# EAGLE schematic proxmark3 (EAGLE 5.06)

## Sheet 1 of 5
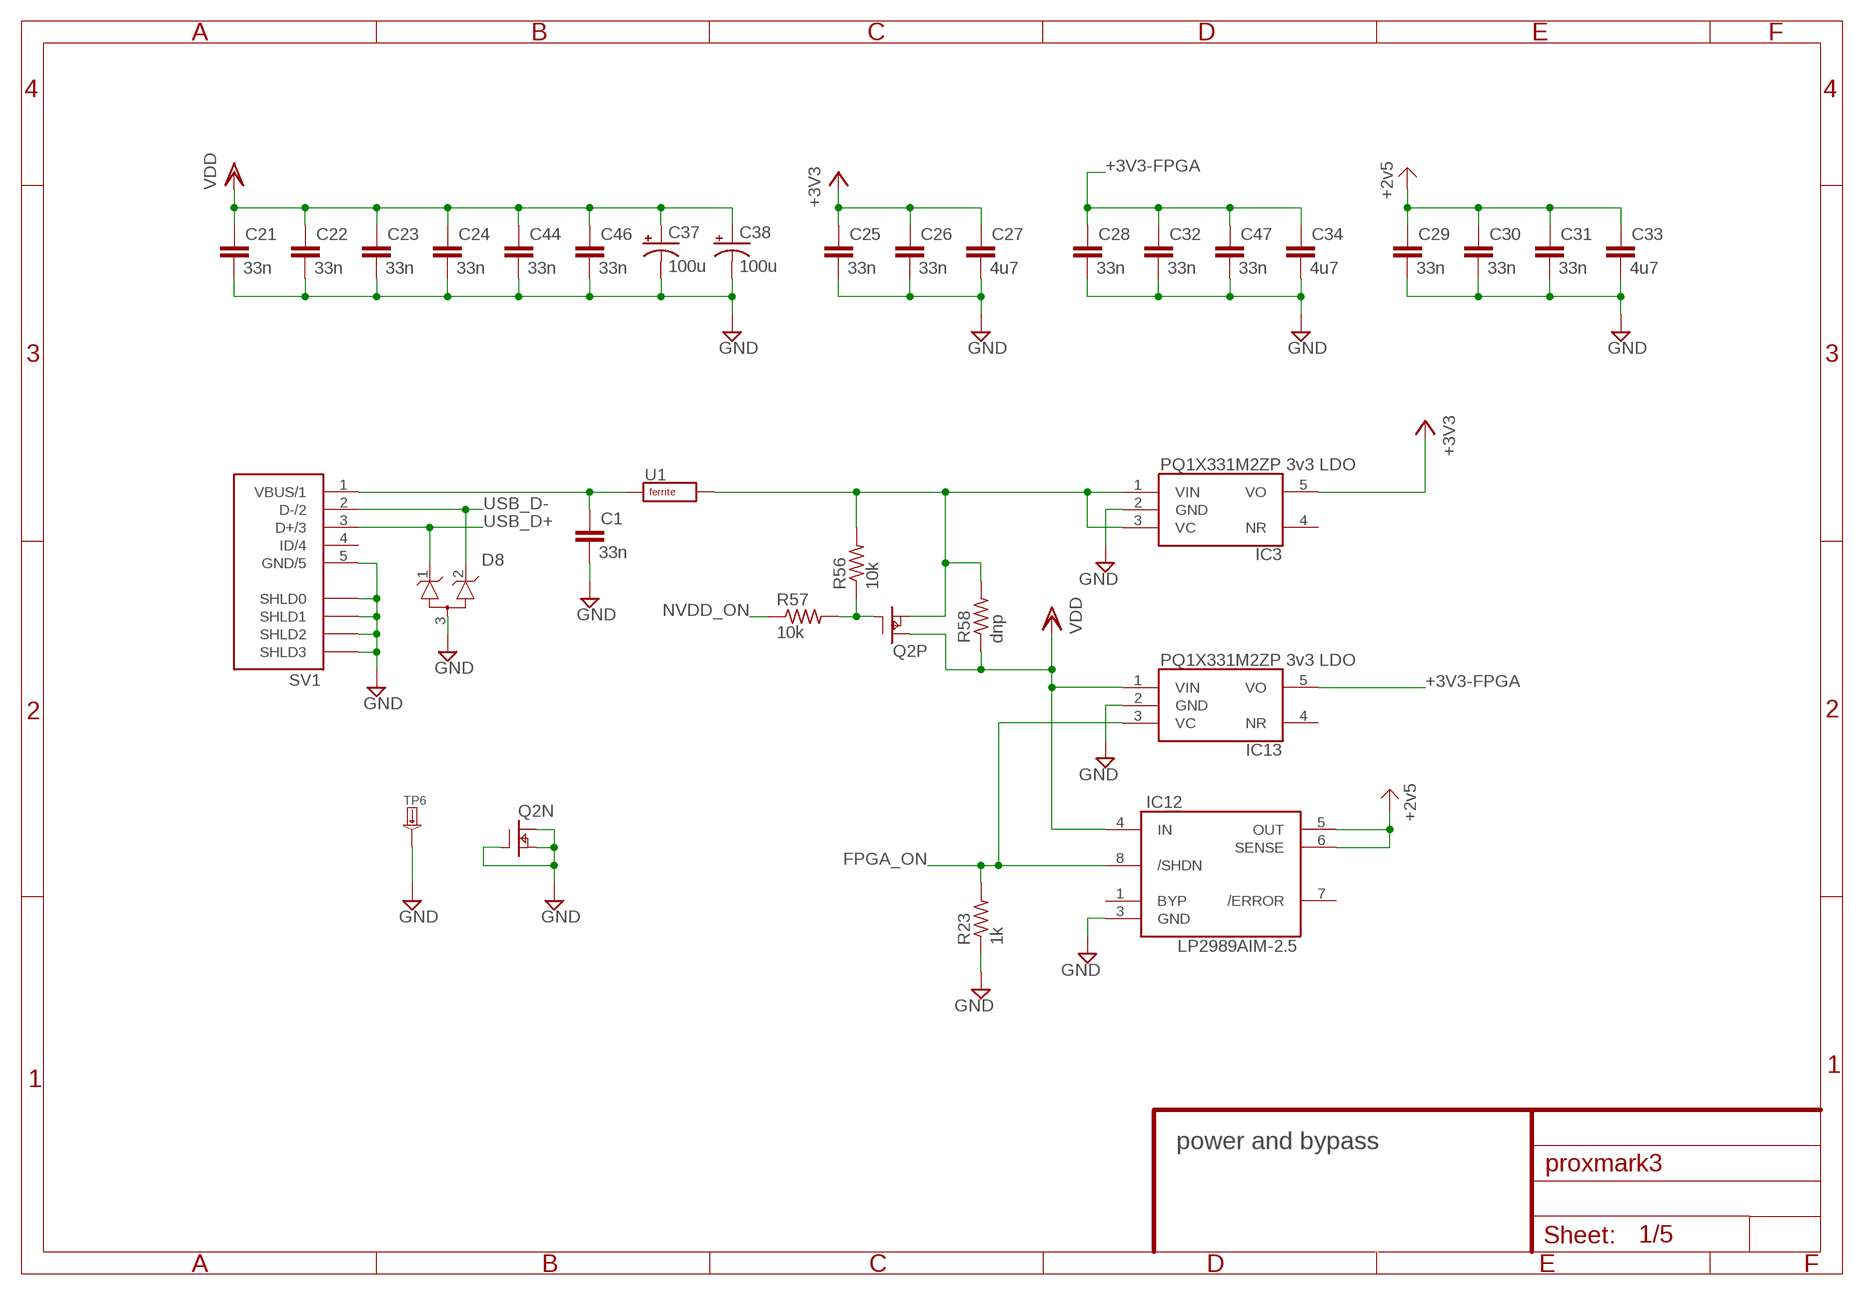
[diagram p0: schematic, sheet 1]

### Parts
C1  33n  CAPACITOR0603  [RLC_0603]
C21  33n  CAPACITOR0603  [RLC_0603]
C22  33n  CAPACITOR0603  [RLC_0603]
C23  33n  CAPACITOR0603  [RLC_0603]
C24  33n  CAPACITOR0603  [RLC_0603]
C25  33n  CAPACITOR0603  [RLC_0603]
C26  33n  CAPACITOR0603  [RLC_0603]
C27  4u7  CAPACITOR1210  [RLC_1210]
C28  33n  CAPACITOR0603  [RLC_0603]
C29  33n  CAPACITOR0603  [RLC_0603]
C30  33n  CAPACITOR0603  [RLC_0603]
C31  33n  CAPACITOR0603  [RLC_0603]
C32  33n  CAPACITOR0603  [RLC_0603]
C33  4u7  CAPACITOR1210  [RLC_1210]
C34  4u7  CAPACITOR1210  [RLC_1210]
C37  100u  CAPACITOR-POLARIZEDALCHIP-MZA-F80  [CAPCAITOR-ELECTROLYTIC-ALCHIP-MZA-F80]
C38  100u  CAPACITOR-POLARIZEDALCHIP-MZA-F80  [CAPCAITOR-ELECTROLYTIC-ALCHIP-MZA-F80]
C44  33n  CAPACITOR0603  [RLC_0603]
C46  33n  CAPACITOR0603  [RLC_0603]
C47  33n  CAPACITOR0603  [RLC_0603]
D8  DUAL-TVS-COMMON-ANODE  [SOT23-3LEAD]
IC3  PQ1X331M2ZP-3V3-LDO-SOT-23-5  [SOT-23-5]
IC12  LP2989AIM-2.5  LP2989-LDOSOIC  [SOIC-8]
IC13  PQ1X331M2ZP-3V3-LDO-SOT-23-5  [SOT-23-5]
Q2  IRF7307  [SOIC-8]
R23  1k  RESISTOR0603  [RLC_0603]
R56  10k  RESISTOR0603  [RLC_0603]
R57  10k  RESISTOR0603  [RLC_0603]
R58  dnp  RESISTOR0603  [RLC_0603]
SV1  USB-MINIB  [USB-MINIB-SMD]
TP6  TESTPADKEYSTONE-PTH  [KEYSTONE-PTH-TESTPOINT-5011]
U1  FERRITE0805  [RLC_0805]

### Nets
+2V5: C29.1 C30.1 C31.1 C33.1 IC12.5(OUT) IC12.6(SENSE) ; supply symbol labelled SUPPLY_2V5 ; also sheet 2
+3V3: C25.1 C26.1 C27.1 IC3.5(VO) ; also sheet 2,3
+3V3-FPGA: C28.1 C32.1 C34.1 C47.1 IC13.5(VO) ; also sheet 2
FPGA_ON: IC12.8(/SHDN) IC13.3(VC) R23.2 ; also sheet 3
GND: C1.2 C21.2 C22.2 C23.2 C24.2 C25.2 C26.2 C27.2 C28.2 C29.2 C30.2 C31.2 C32.2 C33.2 C34.2 C37.- C38.- C44.2 C46.2 C47.2 D8.3(A) IC3.2(GND) IC12.3(GND) IC13.2(GND) Q2.1(N:S) Q2.2(N:G) Q2.8(N:D) R23.1 SV1.5(GND/5) SV1.TAB0(SHLD0) SV1.TAB1(SHLD1) SV1.TAB2(SHLD2) SV1.TAB3(SHLD3) TP6.A ; also sheet 2,3,4,5
N$1: C1.1 SV1.1(VBUS/1) U1.1(A)
N$49: IC3.1(VIN) IC3.3(VC) Q2.3(P:S) R56.2 R58.2 U1.2(B)
NVDD_ON: R57.1 ; also sheet 3
PFETGATE: Q2.4(P:G) R56.1 R57.2
USB_D+: D8.1(K1) SV1.3(D+/3) ; also sheet 3
USB_D-: D8.2(K2) SV1.2(D-/2) ; also sheet 3
VDD: C21.1 C22.1 C23.1 C24.1 C37.+ C38.+ C44.1 C46.1 IC12.4(IN) IC13.1(VIN) Q2.6(P:D) R58.1 ; also sheet 2,4,5
Unconnected: IC3.4(NR) IC12.1(BYP) IC12.7(/ERROR) IC13.4(NR) SV1.4(ID/4)

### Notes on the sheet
- power and bypass

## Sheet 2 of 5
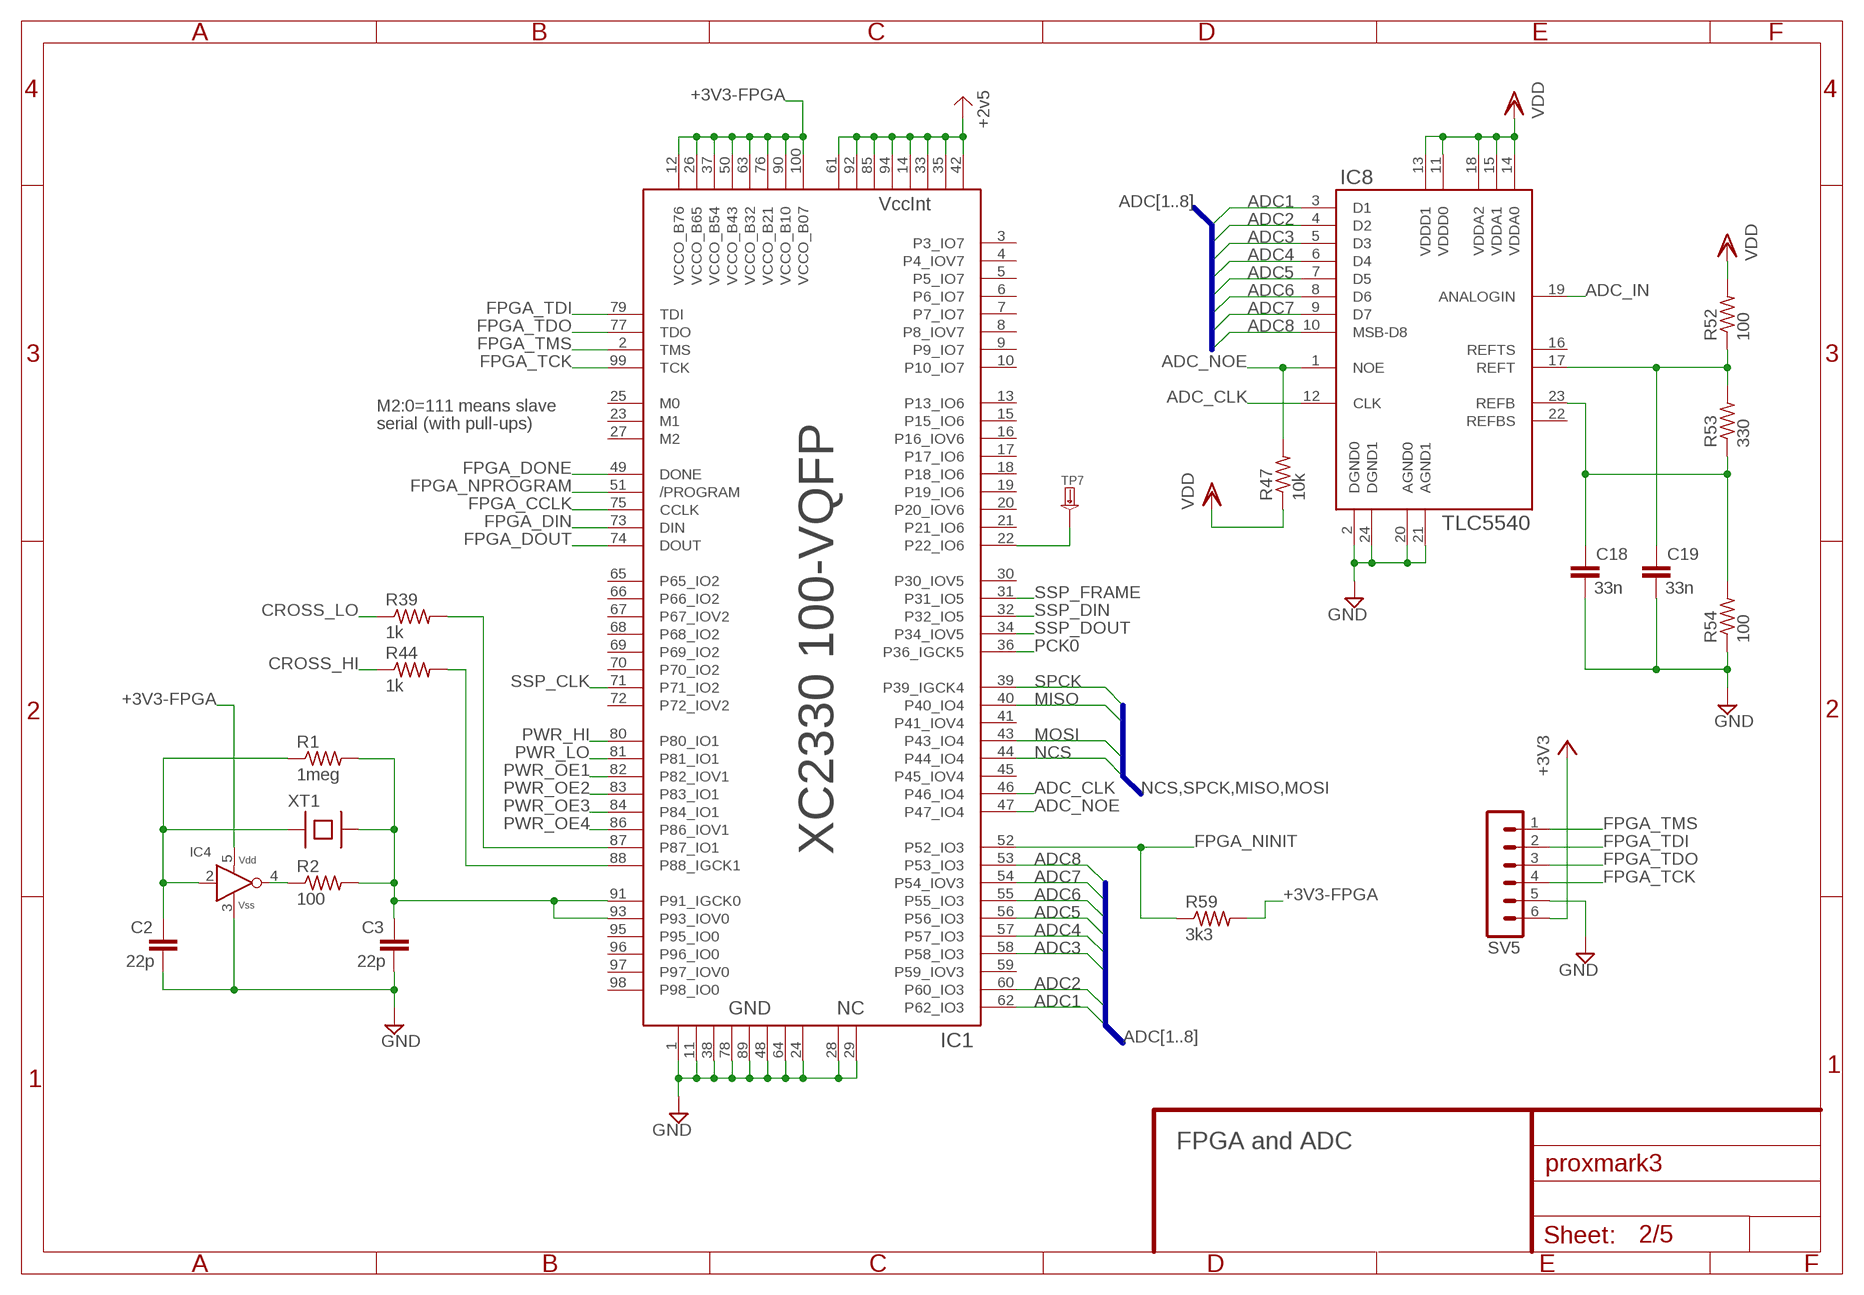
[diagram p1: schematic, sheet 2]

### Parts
C2  22p  CAPACITOR0603  [RLC_0603]
C3  22p  CAPACITOR0603  [RLC_0603]
C18  33n  CAPACITOR0603  [RLC_0603]
C19  33n  CAPACITOR0603  [RLC_0603]
IC1  SPARTAN-II-XC2S30-100-VQFP  [VQFP-100]
IC4  HCU-INVERTER  [SMV-5]
IC8  TLC5540  [TSSOP-24]
R1  1meg  RESISTOR0603  [RLC_0603]
R2  100  RESISTOR0603  [RLC_0603]
R39  1k  RESISTOR0603  [RLC_0603]
R44  1k  RESISTOR0603  [RLC_0603]
R47  10k  RESISTOR0603  [RLC_0603]
R52  100  RESISTOR0603  [RLC_0603]
R53  330  RESISTOR0603  [RLC_0603]
R54  100  RESISTOR0603  [RLC_0603]
R59  3k3  RESISTOR0603  [RLC_0603]
SV5  HEADER-MALE-6X1  [HEADER-MALE-6X1-0.100-UNKEYED]
TP7  TESTPADKEYSTONE-SMD  [KEYSTONE-SMD-TESTPOINT-5015]
XT1  XTAL-SMD-CITIZEN-CS10  [XTAL-SMD-CITIZEN-CS10]

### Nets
+2V5: IC1.14(VCCINT5) IC1.33(VCCINT6) IC1.35(VCCINT7) IC1.42(VCCINT8) IC1.61(VCCINT1) IC1.85(VCCINT3) IC1.92(VCCINT2) IC1.94(VCCINT4) ; supply symbol labelled SUPPLY_2V5 ; also sheet 1
+3V3: SV5.6 ; also sheet 1,3
+3V3-FPGA: IC1.12(VCCO_B76) IC1.26(VCCO_B65) IC1.37(VCCO_B54) IC1.50(VCCO_B43) IC1.63(VCCO_B32) IC1.76(VCCO_B21) IC1.90(VCCO_B10) IC1.100(VCCO_B07) IC4.5(VDD) R59.2 ; also sheet 1
ADC1: IC1.62(P62_IO3) IC8.3(D1)
ADC2: IC1.60(P60_IO3) IC8.4(D2)
ADC3: IC1.58(P58_IO3) IC8.5(D3)
ADC4: IC1.57(P57_IO3) IC8.6(D4)
ADC5: IC1.56(P56_IO3) IC8.7(D5)
ADC6: IC1.55(P55_IO3) IC8.8(D6)
ADC7: IC1.54(P54_IOV3) IC8.9(D7)
ADC8: IC1.53(P53_IO3) IC8.10(MSB-D8)
ADC_CLK: IC1.46(P46_IO4) IC8.12(CLK)
ADC_IN: IC8.19(ANALOGIN) ; also sheet 4
ADC_NOE: IC1.47(P47_IO4) IC8.1(NOE) R47.2
CROSS_HI: R44.1 ; also sheet 4
CROSS_LO: R39.1 ; also sheet 4
FPGA_CCLK: IC1.75(CCLK) ; also sheet 3
FPGA_DIN: IC1.73(DIN) ; also sheet 3
FPGA_DONE: IC1.49(DONE) ; also sheet 3
FPGA_DOUT: IC1.74(DOUT) ; also sheet 3
FPGA_NINIT: IC1.52(P52_IO3) R59.1 ; also sheet 3
FPGA_NPROGRAM: IC1.51(/PROGRAM) ; also sheet 3
FPGA_TCK: IC1.99(TCK) SV5.4
FPGA_TDI: IC1.79(TDI) SV5.2
FPGA_TDO: IC1.77(TDO) SV5.3
FPGA_TMS: IC1.2(TMS) SV5.1
GND: C2.2 C3.2 C18.2 C19.2 IC1.1(GND1) IC1.11(GND2) IC1.24(GND8) IC1.28(NC0) IC1.29(NC1) IC1.38(GND3) IC1.48(GND6) IC1.64(GND7) IC1.78(GND4) IC1.89(GND5) IC4.3(VSS) IC8.2(DGND0) IC8.20(AGND0) IC8.21(AGND1) IC8.24(DGND1) R54.1 SV5.5 ; also sheet 1,3,4,5
MISO: IC1.40(P40_IO4) ; also sheet 3
MOSI: IC1.43(P43_IO4) ; also sheet 3
N$3: IC4.4(Y) R2.1
N$4: C2.1 IC4.2(A) R1.1 XT1.A
N$5: C3.1 IC1.91(P91_IGCK0) IC1.93(P93_IOV0) R1.2 R2.2 XT1.B
N$24: C18.1 IC8.23(REFB) R53.1 R54.2
N$27: IC1.87(P87_IO1) R39.2
N$40: IC1.88(P88_IGCK1) R44.2
N$48: C19.1 IC8.17(REFT) R52.1 R53.2
N$55: IC1.22(P22_IO6) TP7.1
NCS: IC1.44(P44_IO4) ; also sheet 3
PCK0: IC1.36(P36_IGCK5) ; also sheet 3
PWR_HI: IC1.80(P80_IO1) ; also sheet 5
PWR_LO: IC1.81(P81_IO1) ; also sheet 5
PWR_OE1: IC1.82(P82_IOV1) ; also sheet 5
PWR_OE2: IC1.83(P83_IO1) ; also sheet 5
PWR_OE3: IC1.84(P84_IO1) ; also sheet 5
PWR_OE4: IC1.86(P86_IOV1) ; also sheet 5
SPCK: IC1.39(P39_IGCK4) ; also sheet 3
SSP_CLK: IC1.71(P71_IO2) ; also sheet 3
SSP_DIN: IC1.32(P32_IO5) ; also sheet 3
SSP_DOUT: IC1.34(P34_IOV5) ; also sheet 3
SSP_FRAME: IC1.31(P31_IO5) ; also sheet 3
VDD: IC8.11(VDDD0) IC8.13(VDDD1) IC8.14(VDDA0) IC8.15(VDDA1) IC8.18(VDDA2) R47.1 R52.2 ; also sheet 1,4,5
Unconnected: IC1.3(P3_IO7) IC1.4(P4_IOV7) IC1.5(P5_IO7) IC1.6(P6_IO7) IC1.7(P7_IO7) IC1.8(P8_IOV7) IC1.9(P9_IO7) IC1.10(P10_IO7) IC1.13(P13_IO6) IC1.15(P15_IO6) IC1.16(P16_IOV6) IC1.17(P17_IO6) IC1.18(P18_IO6) IC1.19(P19_IO6) IC1.20(P20_IOV6) IC1.21(P21_IO6) IC1.23(M1) IC1.25(M0) IC1.27(M2) IC1.30(P30_IOV5) IC1.41(P41_IOV4) IC1.45(P45_IOV4) IC1.59(P59_IOV3) IC1.65(P65_IO2) IC1.66(P66_IO2) IC1.67(P67_IOV2) IC1.68(P68_IO2) IC1.69(P69_IO2) IC1.70(P70_IO2) IC1.72(P72_IOV2) IC1.95(P95_IO0) IC1.96(P96_IO0) IC1.97(P97_IOV0) IC1.98(P98_IO0) IC8.16(REFTS) IC8.22(REFBS)

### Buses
NCS,SPCK,MISO,MOSI
ADC[1..8]

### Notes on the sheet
- M2:0=111 means slave
- serial (with pull-ups)
- FPGA and ADC

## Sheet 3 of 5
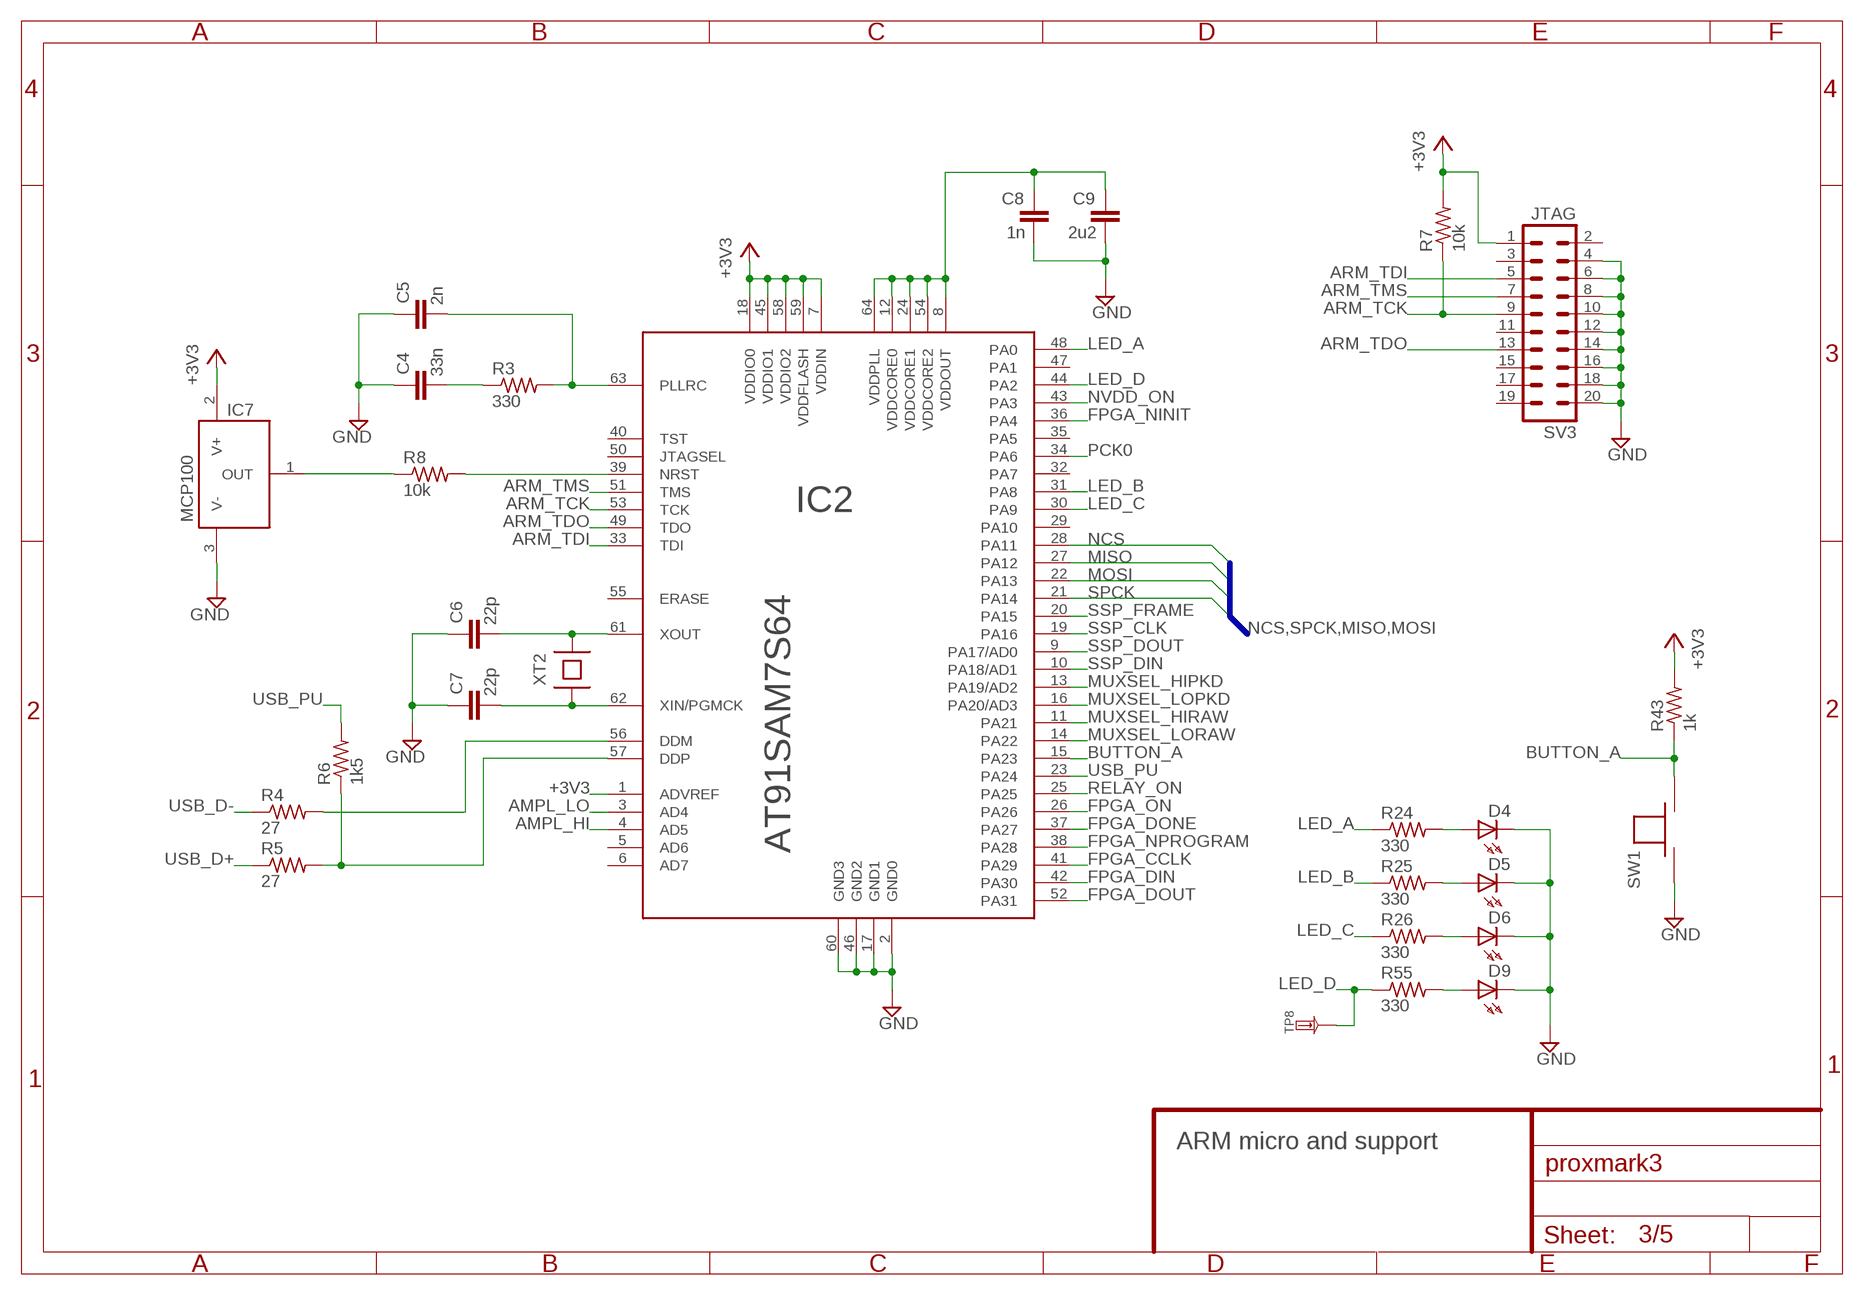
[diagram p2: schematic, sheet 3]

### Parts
C4  33n  CAPACITOR0603  [RLC_0603]
C5  2n  CAPACITOR0603  [RLC_0603]
C6  22p  CAPACITOR0603  [RLC_0603]
C7  22p  CAPACITOR0603  [RLC_0603]
C8  1n  CAPACITOR0603  [RLC_0603]
C9  2u2  CAPACITOR1210  [RLC_1210]
D4  LED  [LED_0603]
D5  LED  [LED_0603]
D6  LED  [LED_0603]
D9  LED  [LED_0603]
IC2  AT91SAM7S64  [LQFP-64]
IC7  MCP100  [SOT23-3LEAD]
R3  330  RESISTOR0603  [RLC_0603]
R4  27  RESISTOR0603  [RLC_0603]
R5  27  RESISTOR0603  [RLC_0603]
R6  1k5  RESISTOR0603  [RLC_0603]
R7  10k  RESISTOR0603  [RLC_0603]
R8  10k  RESISTOR0603  [RLC_0603]
R24  330  RESISTOR0603  [RLC_0603]
R25  330  RESISTOR0603  [RLC_0603]
R26  330  RESISTOR0603  [RLC_0603]
R43  1k  RESISTOR0603  [RLC_0603]
R55  330  RESISTOR0603  [RLC_0603]
SV3  JTAG  HEADER-MALE-10X2  [HEADER-MALE-10X2-0.100-SHROUDED]
SW1  TACTSWITCH  [TACTSWITCH-SMD-EVQQ1]
TP8  TESTPADKEYSTONE-SMD  [KEYSTONE-SMD-TESTPOINT-5015]
XT2  XTAL-SMD-CITIZEN-CS10  [XTAL-SMD-CITIZEN-CS10]

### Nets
+3V3: IC2.1(ADVREF) IC2.7(VDDIN) IC2.18(VDDIO0) IC2.45(VDDIO1) IC2.58(VDDIO2) IC2.59(VDDFLASH) IC7.2(V+) R7.2 R43.2 SV3.1 ; also sheet 1,2
AMPL_HI: IC2.4(AD5) ; also sheet 4
AMPL_LO: IC2.3(AD4) ; also sheet 4
ARM_TCK: IC2.53(TCK) R7.1 SV3.9
ARM_TDI: IC2.33(TDI) SV3.5
ARM_TDO: IC2.49(TDO) SV3.13
ARM_TMS: IC2.51(TMS) SV3.7
BUTTON_A: IC2.15(PA23) R43.1 SW1.B
FPGA_CCLK: IC2.41(PA29) ; also sheet 2
FPGA_DIN: IC2.42(PA30) ; also sheet 2
FPGA_DONE: IC2.37(PA27) ; also sheet 2
FPGA_DOUT: IC2.52(PA31) ; also sheet 2
FPGA_NINIT: IC2.36(PA4) ; also sheet 2
FPGA_NPROGRAM: IC2.38(PA28) ; also sheet 2
FPGA_ON: IC2.26(PA26) ; also sheet 1
GND: C4.1 C5.1 C6.1 C7.1 C8.2 C9.2 D4.-(C) D5.-(C) D6.-(C) D9.-(C) IC2.2(GND0) IC2.17(GND1) IC2.46(GND2) IC2.60(GND3) IC7.3(V-) SV3.4 SV3.6 SV3.8 SV3.10 SV3.12 SV3.14 SV3.16 SV3.18 SV3.20 SW1.A ; also sheet 1,2,4,5
LED_A: IC2.48(PA0) R24.1
LED_B: IC2.31(PA8) R25.1
LED_C: IC2.30(PA9) R26.1
LED_D: IC2.44(PA2) R55.1 TP8.1
MISO: IC2.27(PA12) ; also sheet 2
MOSI: IC2.22(PA13) ; also sheet 2
MUXSEL_HIPKD: IC2.13(PA19/AD2) ; also sheet 4
MUXSEL_HIRAW: IC2.11(PA21) ; also sheet 4
MUXSEL_LOPKD: IC2.16(PA20/AD3) ; also sheet 4
MUXSEL_LORAW: IC2.14(PA22) ; also sheet 4
N$2: C5.2 IC2.63(PLLRC) R3.2
N$6: C4.2 R3.1
N$7: C6.2 IC2.61(XOUT) XT2.B
N$8: C7.2 IC2.62(XIN/PGMCK) XT2.A
N$9: IC2.39(NRST) R8.2
N$10: C8.1 C9.1 IC2.8(VDDOUT) IC2.12(VDDCORE0) IC2.24(VDDCORE1) IC2.54(VDDCORE2) IC2.64(VDDPLL)
N$11: IC2.56(DDM) R4.2
N$12: IC2.57(DDP) R5.2 R6.1
N$13: IC7.1(OUT) R8.1
N$25: D9.+(A) R55.2
N$28: D6.+(A) R26.2
N$29: D5.+(A) R25.2
N$30: D4.+(A) R24.2
NCS: IC2.28(PA11) ; also sheet 2
NVDD_ON: IC2.43(PA3) ; also sheet 1
PCK0: IC2.34(PA6) ; also sheet 2
RELAY_ON: IC2.25(PA25) ; also sheet 4
SPCK: IC2.21(PA14) ; also sheet 2
SSP_CLK: IC2.19(PA16) ; also sheet 2
SSP_DIN: IC2.10(PA18/AD1) ; also sheet 2
SSP_DOUT: IC2.9(PA17/AD0) ; also sheet 2
SSP_FRAME: IC2.20(PA15) ; also sheet 2
USB_D+: R5.1 ; also sheet 1
USB_D-: R4.1 ; also sheet 1
USB_PU: IC2.23(PA24) R6.2
Unconnected: IC2.5(AD6) IC2.6(AD7) IC2.29(PA10) IC2.32(PA7) IC2.35(PA5) IC2.40(TST) IC2.47(PA1) IC2.50(JTAGSEL) IC2.55(ERASE) SV3.2 SV3.3 SV3.11 SV3.15 SV3.17 SV3.19

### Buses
NCS,SPCK,MISO,MOSI

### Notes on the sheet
- ARM micro and support

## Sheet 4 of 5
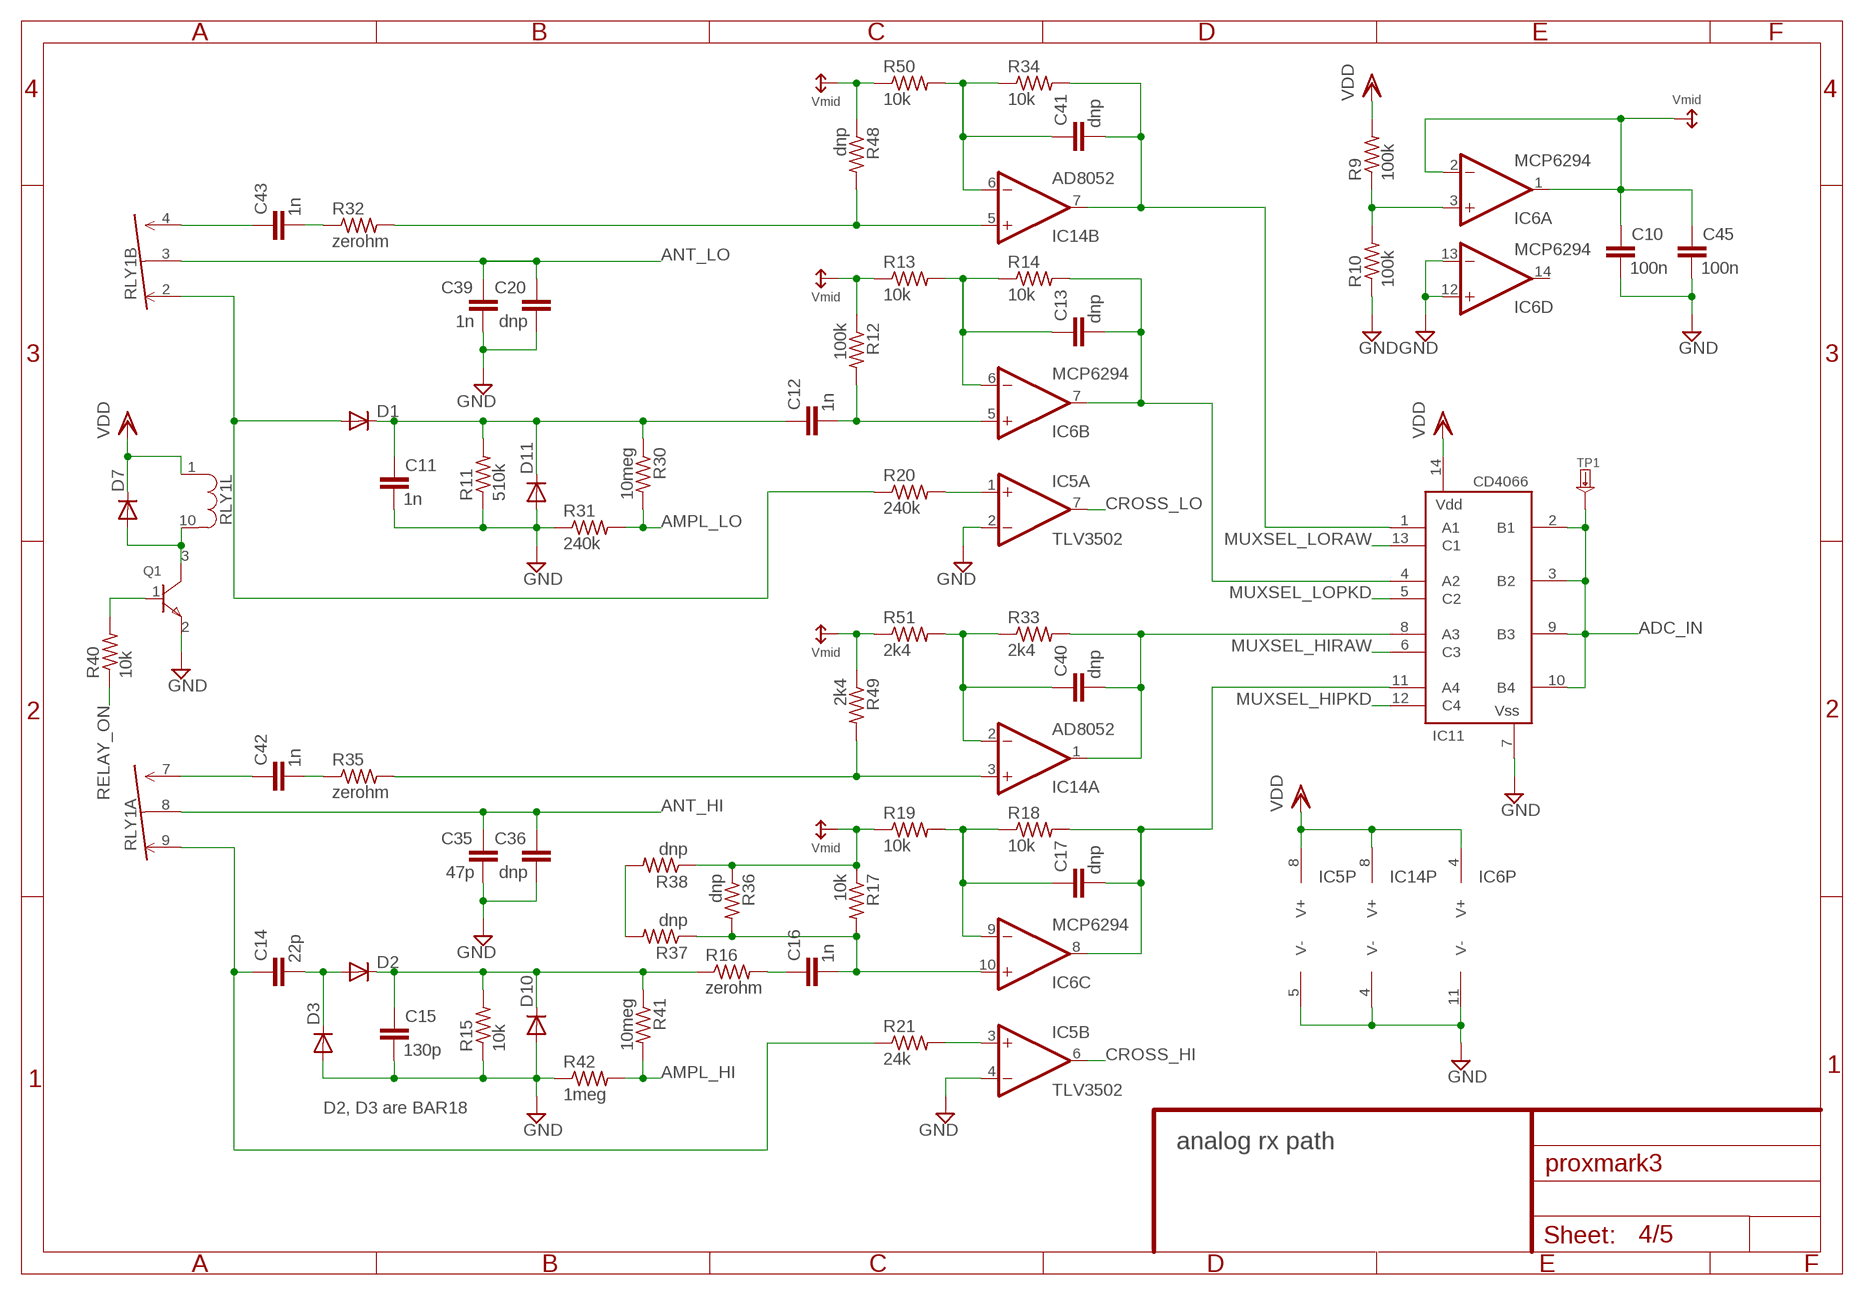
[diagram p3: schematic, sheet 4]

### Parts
C10  100n  CAPACITOR0603  [RLC_0603]
C11  1n  CAPACITOR0603  [RLC_0603]
C12  1n  CAPACITOR0603  [RLC_0603]
C13  dnp  CAPACITOR0603  [RLC_0603]
C14  22p  CAPACITOR0603  [RLC_0603]
C15  130p  CAPACITOR0603  [RLC_0603]
C16  1n  CAPACITOR0603  [RLC_0603]
C17  dnp  CAPACITOR0603  [RLC_0603]
C20  dnp  CAPACITOR0603  [RLC_0603]
C35  47p  CAPACITOR0603  [RLC_0603]
C36  dnp  CAPACITOR0603  [RLC_0603]
C39  1n  CAPACITOR0603  [RLC_0603]
C40  dnp  CAPACITOR0603  [RLC_0603]
C41  dnp  CAPACITOR0603  [RLC_0603]
C42  1n  CAPACITOR0603  [RLC_0603]
C43  1n  CAPACITOR0603  [RLC_0603]
C45  100n  CAPACITOR0603  [RLC_0603]
D1  DIODE-SMD-SOT23  [SOT23-3LEAD]
D2  DIODE-SMD-SOT23  [SOT23-3LEAD]
D3  DIODE-SMD-SOT23  [SOT23-3LEAD]
D7  DIODE-SMD-SOT23  [SOT23-3LEAD]
D10  DIODE-SMD-SOT23  [SOT23-3LEAD]
D11  DIODE-SMD-SOT23  [SOT23-3LEAD]
IC5  TLV3502  COMP-TLV3502SOT-23-8-OR-MSOP-8  [SOT-23-8-OR-MSOP-8]
IC6  MCP6294  OPAMP-TLC2274  [TSSOP-14]
IC11  CD4066  [TSSOP-14]
IC14  AD8052  OPAMP-AD8052  [MSOP8]
Q1  NPN-SOT23-2N3904  [SOT23-3LEAD]
R9  100k  RESISTOR0603  [RLC_0603]
R10  100k  RESISTOR0603  [RLC_0603]
R11  510k  RESISTOR0603  [RLC_0603]
R12  100k  RESISTOR0603  [RLC_0603]
R13  10k  RESISTOR0603  [RLC_0603]
R14  10k  RESISTOR0603  [RLC_0603]
R15  10k  RESISTOR0603  [RLC_0603]
R16  zerohm  RESISTOR0603  [RLC_0603]
R17  10k  RESISTOR0603  [RLC_0603]
R18  10k  RESISTOR0603  [RLC_0603]
R19  10k  RESISTOR0603  [RLC_0603]
R20  240k  RESISTOR0603  [RLC_0603]
R21  24k  RESISTOR0603  [RLC_0603]
R30  10meg  RESISTOR0603  [RLC_0603]
R31  240k  RESISTOR0603  [RLC_0603]
R32  zerohm  RESISTOR0603  [RLC_0603]
R33  2k4  RESISTOR0603  [RLC_0603]
R34  10k  RESISTOR0603  [RLC_0603]
R35  zerohm  RESISTOR0603  [RLC_0603]
R36  dnp  RESISTOR0603  [RLC_0603]
R37  dnp  RESISTOR0603  [RLC_0603]
R38  dnp  RESISTOR0603  [RLC_0603]
R40  10k  RESISTOR0603  [RLC_0603]
R41  10meg  RESISTOR0603  [RLC_0603]
R42  1meg  RESISTOR0603  [RLC_0603]
R48  dnp  RESISTOR0603  [RLC_0603]
R49  2k4  RESISTOR0603  [RLC_0603]
R50  10k  RESISTOR0603  [RLC_0603]
R51  2k4  RESISTOR0603  [RLC_0603]
RLY1  RELAY-DPDT  [TQ-SMD-RELAY]
TP1  TESTPADKEYSTONE-SMD  [KEYSTONE-SMD-TESTPOINT-5015]

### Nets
ADC_IN: IC11.2(B1) IC11.3(B2) IC11.9(B3) IC11.10(B4) TP1.1 ; also sheet 2
ADCDR_HI: C17.2 IC6.8(C:OUT) IC11.11(A4) R18.2
ADCDR_LO: C13.2 IC6.7(B:OUT) IC11.4(A2) R14.2
AMPL_HI: R41.2 R42.2 ; also sheet 3
AMPL_LO: R30.2 R31.2 ; also sheet 3
ANT_HI: C35.1 C36.1 RLY1.8(A:COM) ; also sheet 5
ANT_LO: C20.1 C39.1 RLY1.3(B:COM) ; also sheet 5
CROSS_HI: IC5.6(B:OUT) ; also sheet 2
CROSS_LO: IC5.7(A:OUT) ; also sheet 2
GND: C10.2 C11.2 C15.2 C20.2 C35.2 C36.2 C39.2 C45.2 D3.1(A) D10.1(A) D11.1(A) IC5.2(A:-IN) IC5.4(B:-IN) IC5.5(P:V-) IC6.11(P:V-) IC6.12(D:+IN) IC6.13(D:-IN) IC11.7(VSS) IC14.4(P:V-) Q1.2(E) R10.1 R11.1 R15.1 R31.1 R42.1 ; also sheet 1,2,3,5
MUXSEL_HIPKD: IC11.12(C4) ; also sheet 3
MUXSEL_HIRAW: IC11.6(C3) ; also sheet 3
MUXSEL_LOPKD: IC11.5(C2) ; also sheet 3
MUXSEL_LORAW: IC11.13(C1) ; also sheet 3
N$14: IC6.3(A:+IN) R9.1 R10.2
N$15: C17.1 IC6.9(C:-IN) R18.1 R19.2
N$16: C12.2 IC6.5(B:+IN) R12.2
N$17: C13.1 IC6.6(B:-IN) R13.2 R14.1
N$18: C16.1 R16.2
N$19: C11.1 C12.1 D1.3(C) D11.3(C) R11.2 R30.1
N$20: C14.2 D2.1(A) D3.3(C)
N$21: C15.1 D2.3(C) D10.3(C) R15.2 R16.1 R41.1
N$22: C16.2 IC6.10(C:+IN) R17.2 R36.2 R37.1
N$23: IC5.1(A:+IN) R20.2
N$26: IC5.3(B:+IN) R21.2
N$35: D7.1(A) Q1.3(C) RLY1.10
N$36: C14.1 R21.1 RLY1.9(A:NC)
N$37: C42.1 RLY1.7(A:NO)
N$38: Q1.1(B) R40.2
N$39: D1.1(A) R20.1 RLY1.2(B:NC)
N$43: C41.2 IC11.1(A1) IC14.7(B:OUT) R34.2
N$46: C43.1 RLY1.4(B:NO)
N$47: IC14.3(A:+IN) R35.2 R49.2
N$50: C43.2 R32.1
N$51: C42.2 R35.1
N$52: C40.1 IC14.2(A:-IN) R33.1 R51.2
N$53: C41.1 IC14.6(B:-IN) R34.1 R50.2
N$54: IC14.5(B:+IN) R32.2 R48.2
N$56: R37.2 R38.2
RAW_HI: C40.2 IC11.8(A3) IC14.1(A:OUT) R33.2
RELAY_ON: R40.1 ; also sheet 3
VDD: D7.3(C) IC5.8(P:V+) IC6.4(P:V+) IC11.14(VDD) IC14.8(P:V+) R9.2 RLY1.1 ; also sheet 1,2,5
VMID: C10.1 C45.1 IC6.1(A:OUT) IC6.2(A:-IN) R12.1 R13.1 R17.1 R19.1 R36.1 R38.1 R48.1 R49.1 R50.1 R51.1 ; supply symbol labelled SUPPLY_VMID
Unconnected: IC6.14(D:OUT)

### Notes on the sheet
- D2, D3 are BAR18
- analog rx path

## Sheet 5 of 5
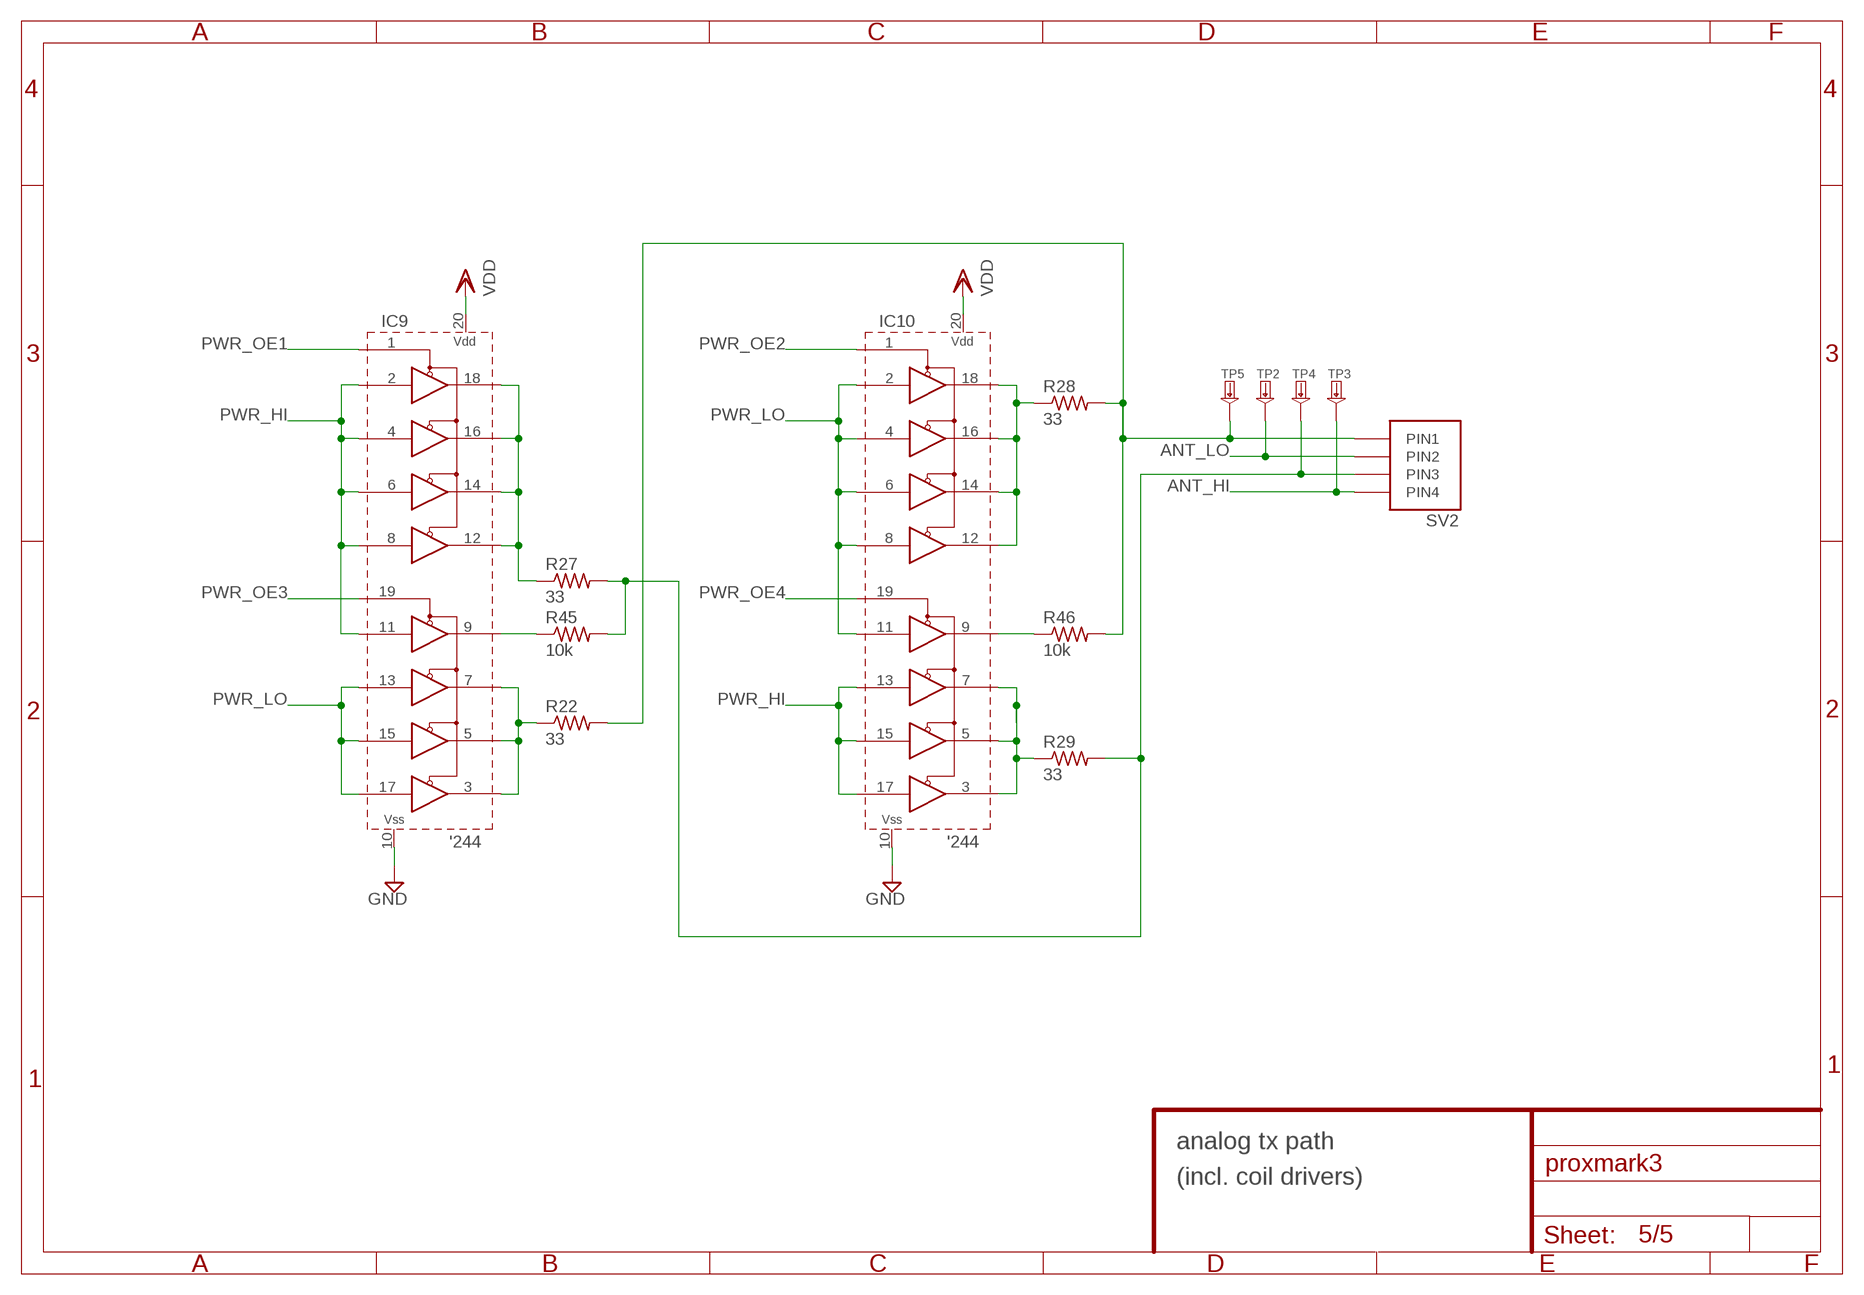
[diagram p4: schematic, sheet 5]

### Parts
IC9  74XX244-OCTAL-TRISTATE-BUFFERS  [TSSOP-20]
IC10  74XX244-OCTAL-TRISTATE-BUFFERS  [TSSOP-20]
R22  33  RESISTOR0603  [RLC_0603]
R27  33  RESISTOR0603  [RLC_0603]
R28  33  RESISTOR0603  [RLC_0603]
R29  33  RESISTOR0603  [RLC_0603]
R45  10k  RESISTOR0603  [RLC_0603]
R46  10k  RESISTOR0603  [RLC_0603]
SV2  HIROSE-MQ172-4POS  [HIROSE-MQ172-4POS]
TP2  TESTPADKEYSTONE-SMD  [KEYSTONE-SMD-TESTPOINT-5015]
TP3  TESTPADKEYSTONE-SMD  [KEYSTONE-SMD-TESTPOINT-5015]
TP4  TESTPADKEYSTONE-SMD  [KEYSTONE-SMD-TESTPOINT-5015]
TP5  TESTPADKEYSTONE-SMD  [KEYSTONE-SMD-TESTPOINT-5015]

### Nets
ANT_HI: SV2.4(PIN4) TP3.1 ; also sheet 4
ANT_LO: SV2.2(PIN2) TP2.1 ; also sheet 4
GND: IC9.10(VSS) IC10.10(VSS) ; also sheet 1,2,3,4
N$31: R27.2 R29.2 R45.2 SV2.3(PIN3) TP4.1
N$32: R22.2 R28.2 R46.2 SV2.1(PIN1) TP5.1
N$33: IC9.12(1Y4) IC9.14(1Y3) IC9.16(1Y2) IC9.18(1Y1) R27.1
N$34: IC10.12(1Y4) IC10.14(1Y3) IC10.16(1Y2) IC10.18(1Y1) R28.1
N$41: IC9.3(2Y4) IC9.5(2Y3) IC9.7(2Y2) R22.1
N$42: IC10.3(2Y4) IC10.5(2Y3) IC10.7(2Y2) R29.1
N$44: IC9.9(2Y1) R45.1
N$45: IC10.9(2Y1) R46.1
PWR_HI: IC9.2(1A1) IC9.4(1A2) IC9.6(1A3) IC9.8(1A4) IC9.11(2A1) IC10.13(2A2) IC10.15(2A3) IC10.17(2A4) ; also sheet 2
PWR_LO: IC9.13(2A2) IC9.15(2A3) IC9.17(2A4) IC10.2(1A1) IC10.4(1A2) IC10.6(1A3) IC10.8(1A4) IC10.11(2A1) ; also sheet 2
PWR_OE1: IC9.1(1NOE) ; also sheet 2
PWR_OE2: IC10.1(1NOE) ; also sheet 2
PWR_OE3: IC9.19(2NOE) ; also sheet 2
PWR_OE4: IC10.19(2NOE) ; also sheet 2
VDD: IC9.20(VDD) IC10.20(VDD) ; also sheet 1,2,4

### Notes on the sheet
- analog tx path
- (incl. coil drivers)

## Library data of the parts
C1-C36 C39-C47 =   merged:CAPACITOR
C37 C38 =   merged:CAPACITOR-POLARIZED
D1-D3 D7 D10 D11 =   merged:DIODE-SMD-SOT23
D4-D6 D9 =   merged:LED
D8 =   merged:DUAL-TVS-COMMON-ANODE
IC1 =   merged:SPARTAN-II-XC2S30-100-VQFP
IC2 =   merged:AT91SAM7S64
IC3 IC13 =   merged:PQ1X331M2ZP-3V3-LDO-SOT-23-5
IC4 =   merged:HCU-INVERTER
IC5 =   merged:COMP-TLV3502
IC6 =   merged:OPAMP-TLC2274
IC7 =   merged:MCP100
IC8 =   merged:TLC5540
IC9 IC10 =   merged:74XX244-OCTAL-TRISTATE-BUFFERS
IC11 =   merged:CD4066
IC12 =   merged:LP2989-LDO
IC14 =   merged:OPAMP-AD8052
Q1 =   merged:NPN-SOT23-2N3904
Q2 =   merged:IRF7307
R1-R59 =   merged:RESISTOR
RLY1 =   merged:RELAY-DPDT
SV1 =   merged:USB-MINIB
SV2 =   merged:HIROSE-MQ172-4POS
SV3 =   merged:HEADER-MALE-10X2
SV5 =   merged:HEADER-MALE-6X1
SW1 =   merged:TACTSWITCH
TP1-TP8 =   merged:TESTPAD
U1 =   merged:FERRITE
XT1 XT2 =   merged:XTAL-SMD-CITIZEN-CS10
